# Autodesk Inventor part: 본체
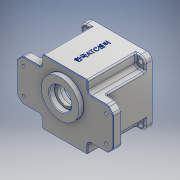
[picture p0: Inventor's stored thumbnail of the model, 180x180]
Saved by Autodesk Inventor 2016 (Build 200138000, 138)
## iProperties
Created: 2017-01
Part Number: 본체
Material: 알루미늄 6061
Document SubType Name: Modeling
Designer: Owner
Mass: 877.343 g
Surface Area: 764.448 cm^2
Volume: 324.942 cm^3
Density: 2.7 g/cm^3
Appearance: 알루미늄 - 평지
Author: Owner
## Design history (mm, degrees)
sketch "스케치1"
  geometry: L1 (47, -47)-(-47, -47); L2 (-47, -47)-(-47, 47); L3 (-47, 47)-(47, 47); L4 (47, 47)-(47, -47); L5 (47, -47)-(-47, 47); L6 (-47, -47)-(47, 47); 1 further point
  constraints: 12 end point, 2 midpoint, 2 parallel, 1 horizontal, 1 perpendicular
  dimensions: "d0" = 94 distance of L2.end L3.end; "d1" = 94 distance of L1.end L2.end
extrude "돌출1" new body sketch "스케치1" distance "d2" = 10; taper "d3" = 0 deg
sketch "스케치2"
  geometry: L1 (-33, -47)-(33, -47); L2 (33, 47)-(-33, 47); L3 (-33, -47)-(33, 47); L4 (33, -47)-(-33, 47); L5 (47, -30)-(47, 30); L6 (-47, 30)-(-47, -30); L7 (-47, -30)-(47, 30); L8 (47, -30)-(-47, 30); L9 (47, 30)-(33, 30); L10 (-33, 30)-(-47, 30); L11 (33, -47)-(33, -30); L12 (33, 30)-(33, 47); L13 (-33, 47)-(-33, 30); L14 (-33, -30)-(-33, -47); L15 (-47, -30)-(-33, -30); L16 (33, -30)-(47, -30); 9 further points
  constraints: 32 end point, 12 midpoint, 10 parallel, 4 perpendicular, 3 horizontal, 2 horizontal alignment, 2 vertical alignment
  dimensions: "d4" = 66 distance of L2.end L2.start; "d5" = 94 distance of L2.start L1.end; "d6" = 94 distance of L6.start L5.end; "d7" = 60 distance of L5.end L5.start
extrude "돌출2" join sketch "스케치2" distance "d8" = 70; taper "d9" = 0 deg
sketch "스케치3"
  geometry: L1 (70, -30)-(70, 30); L2 (-70, 30)-(-70, -30); L3 (-70, -30)-(70, 30); L4 (70, -30)-(-70, 30); L5 (33, -30)-(33, -47) reference; L6 (-33, 47)-(33, 47); L7 (33, -47)-(-33, -47); L8 (-33, 47)-(33, -47); L9 (33, 47)-(-33, -47); L10 (70, 30)-(33, 30); L11 (-33, 30)-(-70, 30); L12 (33, 47)-(33, 30); L13 (33, -30)-(33, -47); L14 (-70, -30)-(-33, -30); L15 (33, -30)-(70, -30); L16 (-33, -47)-(-33, -30); L17 (-33, 30)-(-33, 47); 9 further points
  constraints: 32 end point, 12 midpoint, 10 parallel, 4 perpendicular, 3 horizontal, 2 horizontal alignment, 2 vertical alignment
  dimensions: "d10" = 140 distance of L2.start L1.end; "d11" = 60 distance of L1.end L1.start
extrude "돌출3" join sketch "스케치3" distance "d12" = 13; taper "d13" = 0 deg
sketch "스케치5"
  geometry: 2 further points
  constraints: 1 coincident
hole "구멍1" sketch "스케치5" at (0, 0) diameter "d14" = 80; stored, may be unused: countersink angle "d18" = 90 deg, drill point angle "d20" = 0 deg; dims "d15" = 6, "d16" = 86, "d17" = 9, "d19" = 71
sketch "스케치6"
  geometry: C1 r 21 at (0, -11); 1 further point
  constraints: 1 centre point, 1 vertical alignment
  dimensions: "d21" = 42 diameter of C1; "d22" = 11 distance of point (0, 0) C1.centre
extrude "돌출4" join sketch "스케치6" distance "d23" = 7; taper "d24" = 0 deg
sketch "스케치7"
  geometry: C1 r 15 at (0, 20); 1 further point
  constraints: 1 centre point, 1 vertical alignment
  dimensions: "d25" = 30 diameter of C1; "d26" = 20 distance of point (0, 0) C1.centre
extrude "돌출5" join sketch "스케치7" distance "d27" = 7; taper "d28" = 0 deg
hole "구멍2" diameter "d31" = 35; stored, may be unused: countersink angle "d35" = 90 deg, drill point angle "d37" = 0 deg; dims "d29" = 10, "d30" = 10, "d32" = 6, "d33" = 86, "d34" = 9, "d36" = 10
hole "구멍3" diameter "d40" = 25; stored, may be unused: countersink angle "d44" = 90 deg, drill point angle "d46" = 0 deg; dims "d38" = 10, "d39" = 10, "d41" = 6, "d42" = 86, "d43" = 9, "d45" = 5
sketch "스케치8"
  geometry: C1 r 12.5 at (0, 11) reference; C2 r 17.5 at (0, 11) reference; C3 r 27.5 at (0, 11); 1 further point
  constraints: 1 centre point, 1 coincident
  dimensions: "d47" = 55 diameter of C3
extrude "돌출6" join sketch "스케치8" distance "d48" = 7; taper "d49" = 0 deg
hole "구멍4" diameter "d52" = 32; stored, may be unused: countersink angle "d56" = 90 deg, drill point angle "d58" = 0 deg; dims "d50" = 10, "d51" = 10, "d53" = 6, "d54" = 86, "d55" = 9, "d57" = 8
hole "구멍5" diameter "d61" = 22; stored, may be unused: countersink angle "d65" = 90 deg, drill point angle "d67" = 0 deg; dims "d62" = 6, "d63" = 86, "d64" = 9, "d66" = 7, "d77" = 10, "d78" = 10
hole "구멍6" diameter "d70" = 19; stored, may be unused: countersink angle "d74" = 90 deg, drill point angle "d76" = 0 deg; dims "d68" = 10, "d69" = 10, "d71" = 6, "d72" = 86, "d73" = 9, "d75" = 1
sketch "스케치13"
  geometry: L1 (-36, -4)-(-39.799, -4); L2 (-36, 4)-(-39.799, 4); C1 r 40 at (0, 0) reference; A1 r 4 centre (-36, 0) between (-36, -4) and (-36, 4); A2 r 40 centre (0, 0) between (-39.799, -4) and (-39.799, 4) reference; 1 further point
  constraints: 4 end point, 4 point on circle, 2 horizontal, 2 tangent, 1 centre point, 1 horizontal alignment
  dimensions: "d79" = 8 diameter of A1; "d80" = 36 distance of point (0, 0) A1.centre
extrude "돌출7" join sketch "스케치13" stored distance "d81" = 7; taper "d82" = 0 deg
chamfer "모따기1" distance "d86" = 8; stored, may be unused: second distance "d87" = 2, angle "d88" = 45 deg
fillet "모깎기1" dims "d89" = 5
fillet "모깎기2" dims "d90" = 5
fillet "모깎기3" dims "d91" = 8
sketch "스케치14"
  geometry: L1 (70, -19.929)-(70, 19.929) reference; 2 further points
  dimensions: "d101" = 19 vertical distance of point (0, 0) point (60, -19); "d102" = 10 distance from line of L1 point (60, -19)
hole "구멍8" sketch "스케치14" at (60, -19) diameter "d103" = 4; stored, may be unused: countersink angle "d107" = 90 deg, drill point angle "d109" = 0 deg; dims "d104" = 6, "d105" = 10, "d106" = 4, "d108" = 1
fillet "모깎기4" dims "d110" = 2
fillet "모깎기5" dims "d111" = 2
fillet "모깎기6" dims "d112" = 2
fillet "모깎기7" dims "d113" = 2
sketch "스케치16"
  geometry: L1 (-31, -47)-(31, -47) reference; L2 (33, -45)-(33, -35) reference; L3 (38, -30)-(59.929, -30) reference; L4 (68.536, -23.464)-(63.464, -28.536) reference; L5 (70, 19.929)-(70, -19.929) reference; L6 (63.464, 28.536)-(68.536, 23.464) reference; L7 (38, 30)-(59.929, 30) reference; L8 (33, 35)-(33, 45) reference; L9 (31, 47)-(-31, 47) reference; L10 (-33, 45)-(-33, 35) reference; L11 (-38, 30)-(-59.929, 30) reference; L12 (-68.536, 23.464)-(-63.464, 28.536) reference; L13 (-70, -19.929)-(-70, 19.929) reference; L14 (-63.464, -28.536)-(-68.536, -23.464) reference; L15 (-38, -30)-(-59.929, -30) reference; L16 (-33, -35)-(-33, -45) reference; L17 (-31, 46)-(31, 46); L18 (32, 45)-(32, 35); L19 (38, 29)-(59.929, 29); L20 (62.757, 27.828)-(67.828, 22.757); L21 (69, 19.929)-(69, -19.929); L22 (67.828, -22.757)-(62.757, -27.828); L23 (59.929, -29)-(38, -29); L24 (32, -35)-(32, -45); L25 (31, -46)-(-31, -46); L26 (-32, -45)-(-32, -35); L27 (-38, -29)-(-59.929, -29); L28 (-62.757, -27.828)-(-67.828, -22.757); L29 (-69, -19.929)-(-69, 19.929); L30 (-67.828, 22.757)-(-62.757, 27.828); L31 (-59.929, 29)-(-38, 29); L32 (-32, 35)-(-32, 45); C1 r 2 at (-60, -19) reference; C2 r 2 at (60, -19) reference; C3 r 2 at (-60, 19) reference; C4 r 2 at (60, 19) reference; C5 r 27.5 at (0, 11) reference; A1 r 2 centre (-31, -45) between (-33, -45) and (-31, -47) reference; A2 r 2 centre (31, -45) between (31, -47) and (33, -45) reference; A3 r 5 centre (38, -35) between (38, -30) and (33, -35) reference; A4 r 5 centre (59.929, -25) between (59.929, -30) and (63.464, -28.536) reference; A5 r 5 centre (65, -19.929) between (68.536, -23.464) and (70, -19.929) reference; A6 r 5 centre (65, 19.929) between (70, 19.929) and (68.536, 23.464) reference; A7 r 5 centre (59.929, 25) between (63.464, 28.536) and (59.929, 30) reference; A8 r 5 centre (38, 35) between (33, 35) and (38, 30) reference; A9 r 2 centre (31, 45) between (33, 45) and (31, 47) reference; A10 r 2 centre (-31, 45) between (-31, 47) and (-33, 45) reference; A11 r 5 centre (-38, 35) between (-38, 30) and (-33, 35) reference; A12 r 5 centre (-59.929, 25) between (-59.929, 30) and (-63.464, 28.536) reference; A13 r 5 centre (-65, 19.929) between (-68.536, 23.464) and (-70, 19.929) reference; A14 r 5 centre (-65, -19.929) between (-70, -19.929) and (-68.536, -23.464) reference; A15 r 5 centre (-59.929, -25) between (-63.464, -28.536) and (-59.929, -30) reference; A16 r 5 centre (-38, -35) between (-33, -35) and (-38, -30) reference; A17 r 1 centre (31, 45) between (32, 45) and (31, 46); A18 r 6 centre (38, 35) between (32, 35) and (38, 29); A19 r 4 centre (59.929, 25) between (62.757, 27.828) and (59.929, 29); A20 r 4 centre (65, 19.929) between (69, 19.929) and (67.828, 22.757); A21 r 4 centre (65, -19.929) between (67.828, -22.757) and (69, -19.929); A22 r 4 centre (59.929, -25) between (59.929, -29) and (62.757, -27.828); A23 r 6 centre (38, -35) between (38, -29) and (32, -35); A24 r 1 centre (31, -45) between (31, -46) and (32, -45); A25 r 1 centre (-31, -45) between (-32, -45) and (-31, -46); A26 r 6 centre (-38, -35) between (-32, -35) and (-38, -29); A27 r 4 centre (-59.929, -25) between (-62.757, -27.828) and (-59.929, -29); A28 r 4 centre (-65, -19.929) between (-69, -19.929) and (-67.828, -22.757); A29 r 4 centre (-65, 19.929) between (-67.828, 22.757) and (-69, 19.929); A30 r 4 centre (-59.929, 25) between (-59.929, 29) and (-62.757, 27.828); A31 r 6 centre (-38, 35) between (-38, 29) and (-32, 35); A32 r 1 centre (-31, 45) between (-31, 46) and (-32, 45); 1 further point
  constraints: 32 end point, 32 point on circle, 16 centre point, 31 other
  dimensions: "d114" = 1 distance between parallel lines of L9 L17
extrude "돌출8" cut sketch "스케치16" distance "d115" = 1; taper "d116" = 0 deg
chamfer "모따기2" distance "d117" = 1; stored, may be unused: second distance "d118" = 2, angle "d119" = 45 deg
fillet "모깎기8" dims "d120" = 0.3
fillet "모깎기9" dims "d121" = 0.3
hole "구멍9" diameter "d124" = 3.242; stored, may be unused: countersink angle "d128" = 90 deg, drill point angle "d130" = 118 deg; dims "d125" = 7, "d126" = 10, "d127" = 4, "d129" = 9, "d150" = 10, "d151" = 10
fillet "모깎기10" dims "d134" = 3
fillet "모깎기11" dims "d135" = 3.5
fillet "모깎기12" dims "d136" = 2
sketch "스케치17"
  geometry: 1 further point
fillet "모깎기13" dims "d137" = 1
sketch "스케치18"
  geometry: L1 (0, 0)-(78, 0) reference; 2 further points
  constraints: 1 vertical alignment, 1 other
  dimensions: "d138" = 40 distance from line of L1 point (39, -40)
feature "엠보싱1" sketch "스케치18" dims "d4" = 66, "d5" = 94, "d6" = 94, "d7" = 60, "d139" = 0.5, "d140" = 0
sketch "스케치19"
  geometry: 1 further point
sketch "스케치20"
  geometry: 2 further points
  dimensions: "d141" = 40 horizontal distance of point (0, 0) point (40, 40); "d142" = 40 horizontal distance of point (0, 0) point (40, 40)
hole "구멍10" sketch "스케치20" at (40, 40) diameter "d143" = 7; stored, may be unused: countersink angle "d147" = 90 deg, drill point angle "d149" = 118 deg; dims "d144" = 6, "d145" = 10, "d146" = 4, "d148" = 8
node "솔리드1"
pattern_circular "원형 패턴1" dims angle "d84" = 360 deg
mirror "대칭3"
mirror "대칭4"
pattern_circular "원형 패턴2" dims angle "d132" = 360 deg
mirror "대칭5"
mirror "대칭6"
node "투영된 루프1"
